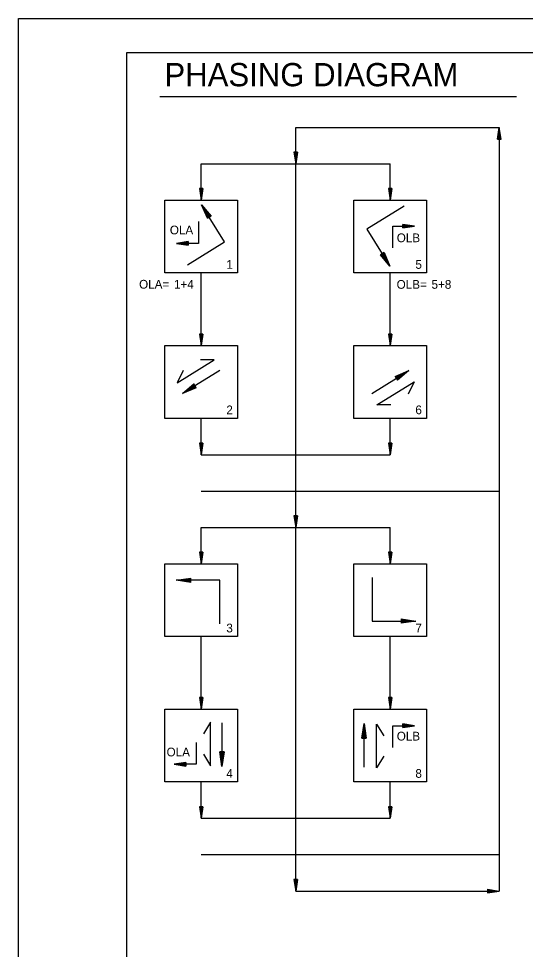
# Model space of a CAD drawing. Extents: x 1712074 to 1713074, y 558397 to 559037.
# Drawn here: x 1712074.1 to 1712248.4, y 558716.9 to 559037 of the extents above; entities that cross this region are included whole.
import ezdxf

# ---------------------------------------------------------------- set-up
doc = ezdxf.new("R2010")
doc.units = 0
for name, color, linetype in [('R_Border', 7, 'Continuous'), ('R_Draft', 7, 'Continuous'), ('R_No Plot', 7, 'Continuous'), ('T_Drafting', 7, 'Continuous'), ('T_Notes', 7, 'Continuous')]:
    doc.layers.add(name, color=color, linetype=linetype)

msp = doc.modelspace()

# ---------------------------------------------------------------- linework, layer by layer
at = {"layer": 'R_Border'}
for p, q in [((1712111.35, 559025.27), (1713059.89, 559025.27)), ((1712111.35, 558408.89), (1712111.35, 559025.27))]:
    msp.add_line(p, q, dxfattribs=at)
at = {"layer": 'R_Draft'}
for p, q in [((1712238.8, 558995.51), (1712239.4, 558999.51)), ((1712238.9, 558995.51), (1712239.4, 558998.84)), ((1712239, 558995.51), (1712239.4, 558998.15)), ((1712239.1, 558995.51), (1712239.4, 558997.49)), ((1712239.2, 558995.51), (1712239.4, 558996.81)), ((1712240, 558995.51), (1712239.4, 558999.51)), ((1712239.9, 558995.51), (1712239.4, 558998.84)), ((1712239.79, 558995.51), (1712239.4, 558998.15)), ((1712239.69, 558995.51), (1712239.4, 558997.49)), ((1712239.59, 558995.51), (1712239.4, 558996.81)), ((1712238.8, 558995.51), (1712240, 558995.51)), ((1712239.3, 558995.51), (1712239.4, 558996.14)), ((1712239.49, 558995.51), (1712239.4, 558996.14)), ((1712168.8, 558991.01), (1712169.4, 558987.01)), ((1712170, 558991.01), (1712168.8, 558991.01)), ((1712168.9, 558991.01), (1712169.4, 558987.68)), ((1712169, 558991.01), (1712169.4, 558988.37)), ((1712169.1, 558991.01), (1712169.4, 558989.03)), ((1712169.2, 558991.01), (1712169.4, 558989.71)), ((1712169.3, 558991.01), (1712169.4, 558990.38)), ((1712170, 558991.01), (1712169.4, 558987.01)), ((1712169.59, 558991.01), (1712169.4, 558989.71)), ((1712169.79, 558991.01), (1712169.4, 558988.37)), ((1712169.9, 558991.01), (1712169.4, 558987.68)), ((1712169.69, 558991.01), (1712169.4, 558989.03)), ((1712169.49, 558991.01), (1712169.4, 558990.38)), ((1712136.3, 558978.51), (1712136.9, 558974.51)), ((1712137.5, 558978.51), (1712136.3, 558978.51)), ((1712136.4, 558978.51), (1712136.9, 558975.18)), ((1712136.5, 558978.51), (1712136.9, 558975.87)), ((1712136.6, 558978.51), (1712136.9, 558976.53)), ((1712136.7, 558978.51), (1712136.9, 558977.21)), ((1712136.8, 558978.51), (1712136.9, 558977.88)), ((1712137.5, 558978.51), (1712136.9, 558974.51)), ((1712137.09, 558978.51), (1712136.9, 558977.21)), ((1712137.29, 558978.51), (1712136.9, 558975.87)), ((1712137.4, 558978.51), (1712136.9, 558975.18)), ((1712137.19, 558978.51), (1712136.9, 558976.53)), ((1712136.99, 558978.51), (1712136.9, 558977.88)), ((1712201.3, 558978.51), (1712201.9, 558974.51)), ((1712202.5, 558978.51), (1712201.3, 558978.51)), ((1712201.4, 558978.51), (1712201.9, 558975.18)), ((1712201.5, 558978.51), (1712201.9, 558975.87)), ((1712201.6, 558978.51), (1712201.9, 558976.53)), ((1712201.7, 558978.51), (1712201.9, 558977.21)), ((1712201.8, 558978.51), (1712201.9, 558977.88)), ((1712202.5, 558978.51), (1712201.9, 558974.51)), ((1712202.09, 558978.51), (1712201.9, 558977.21)), ((1712202.29, 558978.51), (1712201.9, 558975.87)), ((1712202.4, 558978.51), (1712201.9, 558975.18)), ((1712202.19, 558978.51), (1712201.9, 558976.53)), ((1712201.99, 558978.51), (1712201.9, 558977.88)), ((1712136.3, 558928.51), (1712136.9, 558924.51)), ((1712137.5, 558928.51), (1712136.3, 558928.51)), ((1712136.4, 558928.51), (1712136.9, 558925.18)), ((1712136.5, 558928.51), (1712136.9, 558925.87)), ((1712136.6, 558928.51), (1712136.9, 558926.53)), ((1712136.7, 558928.51), (1712136.9, 558927.21)), ((1712136.8, 558928.51), (1712136.9, 558927.88)), ((1712137.5, 558928.51), (1712136.9, 558924.51)), ((1712137.09, 558928.51), (1712136.9, 558927.21)), ((1712137.29, 558928.51), (1712136.9, 558925.87)), ((1712137.4, 558928.51), (1712136.9, 558925.18)), ((1712137.19, 558928.51), (1712136.9, 558926.53)), ((1712136.99, 558928.51), (1712136.9, 558927.88)), ((1712201.3, 558928.51), (1712201.9, 558924.51)), ((1712202.5, 558928.51), (1712201.3, 558928.51)), ((1712201.4, 558928.51), (1712201.9, 558925.18)), ((1712201.5, 558928.51), (1712201.9, 558925.87)), ((1712201.6, 558928.51), (1712201.9, 558926.53)), ((1712201.7, 558928.51), (1712201.9, 558927.21)), ((1712201.8, 558928.51), (1712201.9, 558927.88)), ((1712202.5, 558928.51), (1712201.9, 558924.51)), ((1712202.09, 558928.51), (1712201.9, 558927.21)), ((1712202.29, 558928.51), (1712201.9, 558925.87)), ((1712202.4, 558928.51), (1712201.9, 558925.18)), ((1712202.19, 558928.51), (1712201.9, 558926.53)), ((1712201.99, 558928.51), (1712201.9, 558927.88)), ((1712136.3, 558891.01), (1712136.9, 558887.01)), ((1712137.5, 558891.01), (1712136.3, 558891.01)), ((1712136.4, 558891.01), (1712136.9, 558887.68)), ((1712136.5, 558891.01), (1712136.9, 558888.37)), ((1712136.6, 558891.01), (1712136.9, 558889.03)), ((1712136.7, 558891.01), (1712136.9, 558889.71)), ((1712136.8, 558891.01), (1712136.9, 558890.38)), ((1712137.5, 558891.01), (1712136.9, 558887.01)), ((1712137.09, 558891.01), (1712136.9, 558889.71)), ((1712137.29, 558891.01), (1712136.9, 558888.37)), ((1712137.4, 558891.01), (1712136.9, 558887.68)), ((1712137.19, 558891.01), (1712136.9, 558889.03)), ((1712136.99, 558891.01), (1712136.9, 558890.38)), ((1712201.3, 558891.01), (1712201.9, 558887.01)), ((1712202.5, 558891.01), (1712201.3, 558891.01)), ((1712201.4, 558891.01), (1712201.9, 558887.68)), ((1712201.5, 558891.01), (1712201.9, 558888.37)), ((1712201.6, 558891.01), (1712201.9, 558889.03)), ((1712201.7, 558891.01), (1712201.9, 558889.71)), ((1712201.8, 558891.01), (1712201.9, 558890.38)), ((1712202.5, 558891.01), (1712201.9, 558887.01)), ((1712202.09, 558891.01), (1712201.9, 558889.71)), ((1712202.29, 558891.01), (1712201.9, 558888.37)), ((1712202.4, 558891.01), (1712201.9, 558887.68)), ((1712202.19, 558891.01), (1712201.9, 558889.03)), ((1712201.99, 558891.01), (1712201.9, 558890.38)), ((1712168.8, 558866.01), (1712169.4, 558862.01)), ((1712170, 558866.01), (1712168.8, 558866.01)), ((1712168.9, 558866.01), (1712169.4, 558862.68)), ((1712169, 558866.01), (1712169.4, 558863.37)), ((1712169.1, 558866.01), (1712169.4, 558864.03)), ((1712169.2, 558866.01), (1712169.4, 558864.71)), ((1712169.3, 558866.01), (1712169.4, 558865.38)), ((1712170, 558866.01), (1712169.4, 558862.01)), ((1712169.59, 558866.01), (1712169.4, 558864.71)), ((1712169.79, 558866.01), (1712169.4, 558863.37)), ((1712169.9, 558866.01), (1712169.4, 558862.68)), ((1712169.69, 558866.01), (1712169.4, 558864.03)), ((1712169.49, 558866.01), (1712169.4, 558865.38)), ((1712136.3, 558853.51), (1712136.9, 558849.51)), ((1712137.5, 558853.51), (1712136.3, 558853.51)), ((1712136.4, 558853.51), (1712136.9, 558850.18)), ((1712136.5, 558853.51), (1712136.9, 558850.87)), ((1712136.6, 558853.51), (1712136.9, 558851.53)), ((1712136.7, 558853.51), (1712136.9, 558852.21)), ((1712136.8, 558853.51), (1712136.9, 558852.88)), ((1712137.5, 558853.51), (1712136.9, 558849.51)), ((1712137.09, 558853.51), (1712136.9, 558852.21)), ((1712137.29, 558853.51), (1712136.9, 558850.87)), ((1712137.4, 558853.51), (1712136.9, 558850.18)), ((1712137.19, 558853.51), (1712136.9, 558851.53)), ((1712136.99, 558853.51), (1712136.9, 558852.88)), ((1712201.3, 558853.51), (1712201.9, 558849.51)), ((1712202.5, 558853.51), (1712201.3, 558853.51)), ((1712201.4, 558853.51), (1712201.9, 558850.18)), ((1712201.5, 558853.51), (1712201.9, 558850.87)), ((1712201.6, 558853.51), (1712201.9, 558851.53)), ((1712201.7, 558853.51), (1712201.9, 558852.21)), ((1712201.8, 558853.51), (1712201.9, 558852.88)), ((1712202.5, 558853.51), (1712201.9, 558849.51)), ((1712202.09, 558853.51), (1712201.9, 558852.21)), ((1712202.29, 558853.51), (1712201.9, 558850.87)), ((1712202.4, 558853.51), (1712201.9, 558850.18)), ((1712202.19, 558853.51), (1712201.9, 558851.53)), ((1712201.99, 558853.51), (1712201.9, 558852.88)), ((1712136.3, 558803.51), (1712136.9, 558799.51)), ((1712137.5, 558803.51), (1712136.3, 558803.51)), ((1712136.4, 558803.51), (1712136.9, 558800.18)), ((1712136.5, 558803.51), (1712136.9, 558800.87)), ((1712136.6, 558803.51), (1712136.9, 558801.53)), ((1712136.7, 558803.51), (1712136.9, 558802.21)), ((1712136.8, 558803.51), (1712136.9, 558802.88)), ((1712137.5, 558803.51), (1712136.9, 558799.51)), ((1712137.09, 558803.51), (1712136.9, 558802.21)), ((1712137.29, 558803.51), (1712136.9, 558800.87)), ((1712137.4, 558803.51), (1712136.9, 558800.18)), ((1712137.19, 558803.51), (1712136.9, 558801.53)), ((1712136.99, 558803.51), (1712136.9, 558802.88)), ((1712201.3, 558803.51), (1712201.9, 558799.51)), ((1712202.5, 558803.51), (1712201.3, 558803.51)), ((1712201.4, 558803.51), (1712201.9, 558800.18)), ((1712201.5, 558803.51), (1712201.9, 558800.87)), ((1712201.6, 558803.51), (1712201.9, 558801.53)), ((1712201.7, 558803.51), (1712201.9, 558802.21)), ((1712201.8, 558803.51), (1712201.9, 558802.88)), ((1712202.5, 558803.51), (1712201.9, 558799.51)), ((1712202.09, 558803.51), (1712201.9, 558802.21)), ((1712202.29, 558803.51), (1712201.9, 558800.87)), ((1712202.4, 558803.51), (1712201.9, 558800.18)), ((1712202.19, 558803.51), (1712201.9, 558801.53)), ((1712201.99, 558803.51), (1712201.9, 558802.88)), ((1712136.3, 558766.01), (1712136.9, 558762.01)), ((1712137.5, 558766.01), (1712136.3, 558766.01)), ((1712136.4, 558766.01), (1712136.9, 558762.68)), ((1712136.5, 558766.01), (1712136.9, 558763.37)), ((1712136.6, 558766.01), (1712136.9, 558764.03)), ((1712136.7, 558766.01), (1712136.9, 558764.71)), ((1712136.8, 558766.01), (1712136.9, 558765.38)), ((1712137.5, 558766.01), (1712136.9, 558762.01)), ((1712137.09, 558766.01), (1712136.9, 558764.71)), ((1712137.29, 558766.01), (1712136.9, 558763.37)), ((1712137.4, 558766.01), (1712136.9, 558762.68)), ((1712137.19, 558766.01), (1712136.9, 558764.03)), ((1712136.99, 558766.01), (1712136.9, 558765.38)), ((1712201.3, 558766.01), (1712201.9, 558762.01)), ((1712202.5, 558766.01), (1712201.3, 558766.01)), ((1712201.4, 558766.01), (1712201.9, 558762.68)), ((1712201.5, 558766.01), (1712201.9, 558763.37)), ((1712201.6, 558766.01), (1712201.9, 558764.03)), ((1712201.7, 558766.01), (1712201.9, 558764.71)), ((1712201.8, 558766.01), (1712201.9, 558765.38)), ((1712202.5, 558766.01), (1712201.9, 558762.01)), ((1712202.09, 558766.01), (1712201.9, 558764.71)), ((1712202.29, 558766.01), (1712201.9, 558763.37)), ((1712202.4, 558766.01), (1712201.9, 558762.68)), ((1712202.19, 558766.01), (1712201.9, 558764.03)), ((1712201.99, 558766.01), (1712201.9, 558765.38)), ((1712168.8, 558741.01), (1712169.4, 558737.01)), ((1712170, 558741.01), (1712168.8, 558741.01)), ((1712168.9, 558741.01), (1712169.4, 558737.68)), ((1712169, 558741.01), (1712169.4, 558738.37)), ((1712169.1, 558741.01), (1712169.4, 558739.03)), ((1712169.2, 558741.01), (1712169.4, 558739.71)), ((1712169.3, 558741.01), (1712169.4, 558740.38)), ((1712170, 558741.01), (1712169.4, 558737.01)), ((1712169.59, 558741.01), (1712169.4, 558739.71)), ((1712169.79, 558741.01), (1712169.4, 558738.37)), ((1712169.9, 558741.01), (1712169.4, 558737.68)), ((1712169.69, 558741.01), (1712169.4, 558739.03)), ((1712169.49, 558741.01), (1712169.4, 558740.38)), ((1712235.4, 558737.61), (1712239.4, 558737.01)), ((1712235.4, 558737.61), (1712235.4, 558736.41)), ((1712235.4, 558737.51), (1712238.73, 558737.01)), ((1712235.4, 558737.41), (1712238.04, 558737.01)), ((1712235.4, 558737.31), (1712237.37, 558737.01)), ((1712235.4, 558737.2), (1712236.7, 558737.01)), ((1712235.4, 558737.1), (1712236.03, 558737.01)), ((1712235.4, 558736.41), (1712239.4, 558737.01)), ((1712235.4, 558736.81), (1712236.7, 558737.01)), ((1712235.4, 558736.61), (1712238.04, 558737.01)), ((1712235.4, 558736.51), (1712238.73, 558737.01)), ((1712235.4, 558736.71), (1712237.37, 558737.01)), ((1712235.4, 558736.92), (1712236.03, 558737.01))]:
    msp.add_line(p, q, dxfattribs=at)
at = {"layer": 'R_No Plot'}
msp.add_line((1712074.14, 559036.95), (1713074.14, 559036.95), dxfattribs=at)
msp.add_lwpolyline([(1712074.12, 559036.95), (1713074.14, 559036.95), (1713074.14, 558396.94), (1712074.12, 558396.94)], close=True, dxfattribs=at)
at = {"layer": 'T_Drafting'}
for p, q in [((1712169.4, 558737.01), (1712169.4, 558999.51)), ((1712169.4, 558999.51), (1712239.4, 558999.51)), ((1712239.4, 558999.51), (1712239.4, 558737.01)), ((1712136.9, 558974.51), (1712136.9, 558987.01)), ((1712136.9, 558987.01), (1712201.9, 558987.01)), ((1712201.9, 558974.51), (1712201.9, 558987.01)), ((1712144.94, 558960.18), (1712137.06, 558972.94)), ((1712137.06, 558972.94), (1712140.33, 558969.08)), ((1712139.05, 558968.29), (1712137.06, 558972.94)), ((1712140.22, 558969.02), (1712137.5, 558972.23)), ((1712137.5, 558972.23), (1712139.16, 558968.36)), ((1712137.95, 558971.5), (1712140.11, 558968.95)), ((1712139.26, 558968.43), (1712137.95, 558971.5)), ((1712206.64, 558972.49), (1712193.88, 558964.6)), ((1712140, 558968.88), (1712138.39, 558970.79)), ((1712138.39, 558970.79), (1712139.37, 558968.49)), ((1712138.83, 558970.07), (1712139.9, 558968.82)), ((1712139.48, 558968.56), (1712138.83, 558970.07)), ((1712139.05, 558968.29), (1712140.33, 558969.08)), ((1712139.79, 558968.75), (1712139.27, 558969.36)), ((1712139.27, 558969.36), (1712139.59, 558968.63)), ((1712135.92, 558967.19), (1712135.92, 558959.69)), ((1712202.79, 558958.11), (1712202.79, 558965.61)), ((1712202.79, 558965.61), (1712210.29, 558965.61)), ((1712210.29, 558965.61), (1712206.29, 558966.21)), ((1712206.29, 558965.01), (1712206.29, 558966.21)), ((1712206.29, 558966.11), (1712209.62, 558965.61)), ((1712208.93, 558965.61), (1712206.29, 558966.01)), ((1712206.29, 558965.91), (1712208.27, 558965.61)), ((1712207.59, 558965.61), (1712206.29, 558965.8)), ((1712206.29, 558965.7), (1712206.92, 558965.61)), ((1712206.92, 558965.61), (1712206.29, 558965.51)), ((1712206.29, 558965.41), (1712207.59, 558965.61)), ((1712208.27, 558965.61), (1712206.29, 558965.31)), ((1712206.29, 558965.21), (1712208.93, 558965.61)), ((1712209.62, 558965.61), (1712206.29, 558965.11)), ((1712206.29, 558965.01), (1712210.29, 558965.61)), ((1712193.88, 558964.6), (1712201.77, 558951.84)), ((1712132.42, 558960.29), (1712128.42, 558959.69)), ((1712135.92, 558959.69), (1712128.42, 558959.69)), ((1712128.42, 558959.69), (1712132.42, 558959.09)), ((1712129.09, 558959.69), (1712132.42, 558960.19)), ((1712132.42, 558959.19), (1712129.09, 558959.69)), ((1712132.42, 558960.09), (1712129.77, 558959.69)), ((1712129.77, 558959.69), (1712132.42, 558959.29)), ((1712130.44, 558959.69), (1712132.42, 558959.99)), ((1712132.42, 558959.39), (1712130.44, 558959.69)), ((1712132.42, 558959.88), (1712131.12, 558959.69)), ((1712131.12, 558959.69), (1712132.42, 558959.49)), ((1712131.79, 558959.69), (1712132.42, 558959.78)), ((1712132.42, 558959.6), (1712131.79, 558959.69)), ((1712132.18, 558952.3), (1712144.94, 558960.18)), ((1712132.42, 558960.29), (1712132.42, 558959.09)), ((1712199.78, 558956.49), (1712198.5, 558955.7)), ((1712201.77, 558951.84), (1712198.5, 558955.7)), ((1712198.61, 558955.77), (1712201.33, 558952.55)), ((1712200.88, 558953.28), (1712198.71, 558955.83)), ((1712198.82, 558955.9), (1712200.44, 558953.99)), ((1712199.99, 558954.71), (1712198.93, 558955.97)), ((1712199.04, 558956.03), (1712199.55, 558955.42)), ((1712199.55, 558955.42), (1712199.24, 558956.16)), ((1712199.34, 558956.22), (1712199.99, 558954.71)), ((1712200.44, 558953.99), (1712199.45, 558956.29)), ((1712199.56, 558956.36), (1712200.88, 558953.28)), ((1712201.33, 558952.55), (1712199.67, 558956.42)), ((1712199.78, 558956.49), (1712201.77, 558951.84)), ((1712136.9, 558924.51), (1712136.9, 558949.51)), ((1712201.9, 558924.51), (1712201.9, 558949.51)), ((1712143.28, 558915.95), (1712130.52, 558908.07)), ((1712195.52, 558908.07), (1712208.28, 558915.95)), ((1712203.63, 558913.96), (1712208.28, 558915.95)), ((1712203.63, 558913.96), (1712204.42, 558912.69)), ((1712207.57, 558915.51), (1712203.69, 558913.86)), ((1712203.76, 558913.75), (1712206.83, 558915.06)), ((1712206.13, 558914.62), (1712203.83, 558913.64)), ((1712203.89, 558913.53), (1712205.4, 558914.18)), ((1712204.69, 558913.74), (1712203.96, 558913.42)), ((1712204.08, 558913.22), (1712204.69, 558913.74)), ((1712205.4, 558914.18), (1712204.15, 558913.12)), ((1712204.22, 558913.01), (1712206.13, 558914.62)), ((1712206.83, 558915.06), (1712204.28, 558912.9)), ((1712204.35, 558912.79), (1712207.57, 558915.51)), ((1712208.28, 558915.95), (1712204.42, 558912.69)), ((1712130.52, 558908.07), (1712134.37, 558911.33)), ((1712134.44, 558911.23), (1712131.23, 558908.51)), ((1712131.96, 558908.96), (1712134.51, 558911.12)), ((1712134.57, 558911.01), (1712132.67, 558909.4)), ((1712132.67, 558909.4), (1712134.96, 558910.38)), ((1712133.39, 558909.84), (1712134.64, 558910.9)), ((1712134.9, 558910.49), (1712133.39, 558909.84)), ((1712134.71, 558910.8), (1712134.1, 558910.28)), ((1712134.1, 558910.28), (1712134.83, 558910.6)), ((1712135.16, 558910.06), (1712134.37, 558911.33)), ((1712135.16, 558910.06), (1712130.52, 558908.07)), ((1712131.23, 558908.51), (1712135.1, 558910.16)), ((1712135.03, 558910.27), (1712131.96, 558908.96)), ((1712136.9, 558887.01), (1712136.9, 558899.51)), ((1712201.9, 558887.01), (1712201.9, 558899.51)), ((1712136.9, 558887.01), (1712201.9, 558887.01)), ((1712136.9, 558874.51), (1712239.4, 558874.51)), ((1712136.9, 558862.01), (1712201.9, 558862.01)), ((1712136.9, 558849.51), (1712136.9, 558862.01)), ((1712201.9, 558849.51), (1712201.9, 558862.01)), ((1712128.34, 558843.85), (1712133.34, 558844.6)), ((1712143.34, 558843.85), (1712128.34, 558843.85)), ((1712133.34, 558843.1), (1712128.34, 558843.85)), ((1712133.34, 558844.47), (1712129.18, 558843.85)), ((1712129.18, 558843.85), (1712133.34, 558843.22)), ((1712130.04, 558843.85), (1712133.34, 558844.35)), ((1712133.34, 558843.35), (1712130.04, 558843.85)), ((1712133.34, 558844.22), (1712130.87, 558843.85)), ((1712130.87, 558843.85), (1712133.34, 558843.48)), ((1712131.72, 558843.85), (1712133.34, 558844.09)), ((1712133.34, 558843.61), (1712131.72, 558843.85)), ((1712133.34, 558843.97), (1712132.55, 558843.85)), ((1712132.55, 558843.85), (1712133.34, 558843.73)), ((1712133.34, 558843.1), (1712133.34, 558844.6)), ((1712143.34, 558828.85), (1712143.34, 558843.85)), ((1712195.68, 558844.8), (1712195.68, 558829.8)), ((1712205.68, 558830.55), (1712210.68, 558829.8)), ((1712205.68, 558830.55), (1712205.68, 558829.05)), ((1712209.85, 558829.8), (1712205.68, 558830.42)), ((1712195.68, 558829.8), (1712210.68, 558829.8)), ((1712205.68, 558830.3), (1712208.99, 558829.8)), ((1712208.16, 558829.8), (1712205.68, 558830.17)), ((1712205.68, 558830.04), (1712207.31, 558829.8)), ((1712206.47, 558829.8), (1712205.68, 558829.92)), ((1712210.68, 558829.8), (1712205.68, 558829.05)), ((1712205.68, 558829.17), (1712209.85, 558829.8)), ((1712208.99, 558829.8), (1712205.68, 558829.3)), ((1712205.68, 558829.43), (1712208.16, 558829.8)), ((1712207.31, 558829.8), (1712205.68, 558829.55)), ((1712205.68, 558829.68), (1712206.47, 558829.8)), ((1712136.9, 558799.51), (1712136.9, 558824.51)), ((1712201.9, 558799.51), (1712201.9, 558824.51)), ((1712144.02, 558794.84), (1712144.02, 558779.84)), ((1712192.16, 558789.62), (1712192.91, 558794.62)), ((1712192.91, 558793.79), (1712192.28, 558789.62)), ((1712192.41, 558789.62), (1712192.91, 558792.93)), ((1712192.91, 558792.09), (1712192.54, 558789.62)), ((1712192.91, 558779.62), (1712192.91, 558794.62)), ((1712192.91, 558794.62), (1712193.66, 558789.62)), ((1712193.53, 558789.62), (1712192.91, 558793.79)), ((1712192.91, 558792.93), (1712193.41, 558789.62)), ((1712193.28, 558789.62), (1712192.91, 558792.09)), ((1712202.79, 558786.34), (1712202.79, 558793.84)), ((1712202.79, 558793.84), (1712210.29, 558793.84)), ((1712210.29, 558793.84), (1712206.29, 558794.44)), ((1712206.29, 558793.24), (1712206.29, 558794.44)), ((1712206.29, 558794.34), (1712209.62, 558793.84)), ((1712208.93, 558793.84), (1712206.29, 558794.24)), ((1712206.29, 558794.14), (1712208.27, 558793.84)), ((1712207.59, 558793.84), (1712206.29, 558794.03)), ((1712206.29, 558793.93), (1712206.92, 558793.84)), ((1712206.92, 558793.84), (1712206.29, 558793.74)), ((1712206.29, 558793.64), (1712207.59, 558793.84)), ((1712208.27, 558793.84), (1712206.29, 558793.54)), ((1712206.29, 558793.44), (1712208.93, 558793.84)), ((1712209.62, 558793.84), (1712206.29, 558793.34)), ((1712206.29, 558793.24), (1712210.29, 558793.84)), ((1712192.16, 558789.62), (1712193.66, 558789.62)), ((1712192.67, 558789.62), (1712192.91, 558791.25)), ((1712192.91, 558790.41), (1712192.79, 558789.62)), ((1712192.91, 558791.25), (1712193.15, 558789.62)), ((1712193.03, 558789.62), (1712192.91, 558790.41)), ((1712135.12, 558788.09), (1712135.12, 558780.59)), ((1712144.02, 558779.84), (1712143.27, 558784.84)), ((1712144.77, 558784.84), (1712143.27, 558784.84)), ((1712143.4, 558784.84), (1712144.02, 558780.68)), ((1712144.02, 558781.54), (1712143.52, 558784.84)), ((1712143.65, 558784.84), (1712144.02, 558782.37)), ((1712144.02, 558783.22), (1712143.78, 558784.84)), ((1712143.9, 558784.84), (1712144.02, 558784.05)), ((1712144.02, 558784.05), (1712144.14, 558784.84)), ((1712144.26, 558784.84), (1712144.02, 558783.22)), ((1712144.02, 558782.37), (1712144.39, 558784.84)), ((1712144.52, 558784.84), (1712144.02, 558781.54)), ((1712144.02, 558780.68), (1712144.65, 558784.84)), ((1712144.77, 558784.84), (1712144.02, 558779.84)), ((1712131.62, 558781.19), (1712127.62, 558780.59)), ((1712135.12, 558780.59), (1712127.62, 558780.59)), ((1712127.62, 558780.59), (1712131.62, 558779.99)), ((1712128.29, 558780.59), (1712131.62, 558781.09)), ((1712131.62, 558780.09), (1712128.29, 558780.59)), ((1712131.62, 558780.99), (1712128.98, 558780.59)), ((1712128.98, 558780.59), (1712131.62, 558780.19)), ((1712129.64, 558780.59), (1712131.62, 558780.89)), ((1712131.62, 558780.29), (1712129.64, 558780.59)), ((1712131.62, 558780.78), (1712130.32, 558780.59)), ((1712130.32, 558780.59), (1712131.62, 558780.39)), ((1712130.99, 558780.59), (1712131.62, 558780.68)), ((1712131.62, 558780.5), (1712130.99, 558780.59)), ((1712131.62, 558781.19), (1712131.62, 558779.99)), ((1712136.9, 558762.01), (1712136.9, 558774.51)), ((1712201.9, 558762.01), (1712201.9, 558774.51)), ((1712136.9, 558762.01), (1712201.9, 558762.01)), ((1712136.9, 558749.51), (1712239.4, 558749.51)), ((1712169.4, 558737.01), (1712239.4, 558737.01))]:
    msp.add_line(p, q, dxfattribs=at)
for points in [[(1712124.4, 558974.51), (1712149.4, 558974.51), (1712149.4, 558949.51), (1712124.4, 558949.51)], [(1712189.4, 558974.51), (1712214.4, 558974.51), (1712214.4, 558949.51), (1712189.4, 558949.51)], [(1712124.4, 558924.51), (1712149.4, 558924.51), (1712149.4, 558899.51), (1712124.4, 558899.51)], [(1712189.4, 558924.51), (1712214.4, 558924.51), (1712214.4, 558899.51), (1712189.4, 558899.51)], [(1712124.4, 558849.51), (1712149.4, 558849.51), (1712149.4, 558824.51), (1712124.4, 558824.51)], [(1712189.4, 558849.51), (1712214.4, 558849.51), (1712214.4, 558824.51), (1712189.4, 558824.51)], [(1712124.4, 558799.51), (1712149.4, 558799.51), (1712149.4, 558774.51), (1712124.4, 558774.51)], [(1712189.4, 558799.51), (1712214.4, 558799.51), (1712214.4, 558774.51), (1712189.4, 558774.51)]]:
    msp.add_lwpolyline(points, close=True, dxfattribs=at)
for points in [[(1712130.74, 558915.99), (1712128.66, 558911.76), (1712141.42, 558919.65), (1712136.7, 558919.67)], [(1712202.07, 558904.14), (1712197.35, 558904.17), (1712210.11, 558912.05), (1712208.02, 558907.82)], [(1712137.65, 558784.01), (1712140.15, 558780.01), (1712140.15, 558795.01), (1712137.65, 558791.01)], [(1712199.66, 558783.34), (1712197.16, 558779.34), (1712197.16, 558794.34), (1712199.66, 558790.34)]]:
    msp.add_lwpolyline(points, dxfattribs=at)
at = {"layer": 'T_Notes'}
msp.add_line((1712122.67, 559010.22), (1712245.32, 559010.22), dxfattribs=at)

# ---------------------------------------------------------------- texts
at = {"layer": 'T_Drafting'}
for s, p in [('OLA', (1712126.12, 558962.78)), ('OLB', (1712204.15, 558960.08)), ('OLA=', (1712115.55, 558944.12)), ('1+4', (1712127.55, 558944.12)), ('OLB=', (1712204.11, 558944.07)), ('5+8', (1712216.11, 558944.07)), ('OLB', (1712204.15, 558788.76)), ('OLA', (1712125.01, 558783.3))]:
    msp.add_text(s, height=3, dxfattribs=at).set_placement(p)
at = {"layer": 'T_Notes'}
for s, height, p in [('PHASING DIAGRAM', 8, (1712124.27, 559013.69)), ('1', 3, (1712145.55, 558950.93)), ('5', 3, (1712210.55, 558950.93)), ('2', 3, (1712145.55, 558900.93)), ('6', 3, (1712210.55, 558900.93)), ('3', 3, (1712145.55, 558825.93)), ('7', 3, (1712210.55, 558825.93)), ('4', 3, (1712145.55, 558775.93)), ('8', 3, (1712210.55, 558775.93))]:
    msp.add_text(s, height=height, dxfattribs=at).set_placement(p)

doc.saveas('drawing.dxf')
